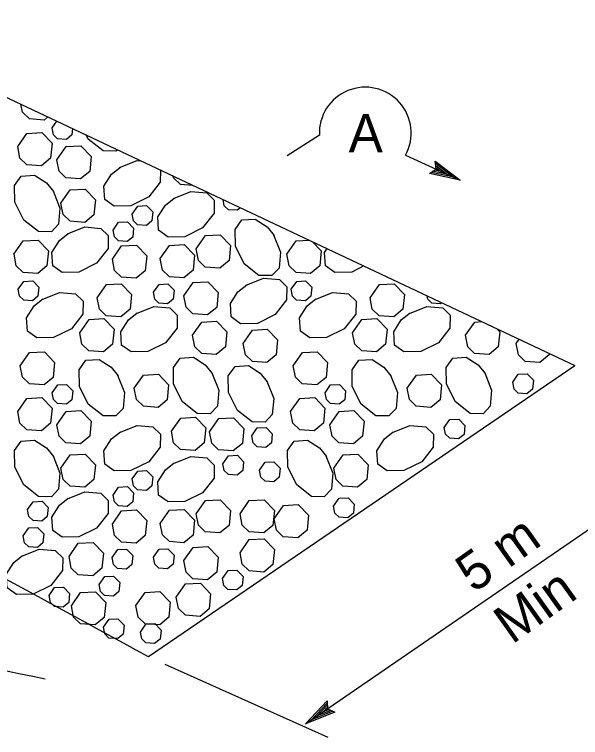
# Model space of a CAD drawing. Extents: x 6707406 to 6714471, y 1868570 to 1872341.
# Drawn here: x 6710751.9 to 6710858.1, y 1870263.6 to 1870399.2 of the extents above; entities that cross this region are included whole.
import ezdxf

# ---------------------------------------------------------------- set-up
doc = ezdxf.new("R2010")
doc.units = 0
for name, color, linetype in [('56 Stg 3 Anno', 7, 'Continuous'), ('57 Undefined', 7, 'Continuous'), ('60 Nongeo Data', 7, 'Continuous')]:
    doc.layers.add(name, color=color, linetype=linetype)

msp = doc.modelspace()

# ---------------------------------------------------------------- linework, layer by layer
at = {"layer": '56 Stg 3 Anno'}
for p, q in [((6710809.08, 1870376.54), (6710803.05, 1870372.66)), ((6710825.26, 1870372.79), (6710835.51, 1870368.07)), ((6710830.97, 1870370.16), (6710830.81, 1870371.65)), ((6710830.81, 1870371.65), (6710830.81, 1870371.65)), ((6710830.81, 1870371.65), (6710835.51, 1870368.07)), ((6710830.86, 1870371.26), (6710834.31, 1870368.63)), ((6710830.92, 1870370.85), (6710833.1, 1870369.18)), ((6710830.94, 1870370.47), (6710831.9, 1870369.74)), ((6710829.74, 1870369.32), (6710830.97, 1870370.16)), ((6710835.51, 1870368.07), (6710829.74, 1870369.32)), ((6710829.74, 1870369.32), (6710829.74, 1870369.32)), ((6710834.3, 1870368.63), (6710830.09, 1870369.54)), ((6710833.1, 1870369.18), (6710830.38, 1870369.77)), ((6710831.9, 1870369.74), (6710830.74, 1870369.99)), ((6710835.51, 1870368.07), (6710835.51, 1870368.07)), ((6710806.49, 1870266.16), (6710885.13, 1870320.15)), ((6710810.73, 1870263.58), (6710780.13, 1870277.31)), ((6710806.49, 1870266.16), (6710810.52, 1870270.48)), ((6710807.59, 1870266.92), (6710810.53, 1870270.06)), ((6710810.52, 1870270.48), (6710810.52, 1870270.48)), ((6710810.52, 1870270.48), (6710810.61, 1870268.99)), ((6710811.6, 1870268.53), (6710807.59, 1870266.91)), ((6710808.68, 1870267.66), (6710810.58, 1870269.69)), ((6710811.22, 1870268.68), (6710808.68, 1870267.66)), ((6710809.77, 1870268.41), (6710810.59, 1870269.28)), ((6710810.9, 1870268.86), (6710809.77, 1870268.41)), ((6710810.61, 1870268.99), (6710811.97, 1870268.36)), ((6710811.97, 1870268.36), (6710806.49, 1870266.16)), ((6710811.97, 1870268.36), (6710811.97, 1870268.36)), ((6710806.49, 1870266.16), (6710806.49, 1870266.16))]:
    msp.add_line(p, q, dxfattribs=at)
msp.add_arc((6710817.69, 1870376.91), 8.62, 331.4936, 182.464, dxfattribs=at)
at = {"layer": '60 Nongeo Data'}
for p, q in [((6710717.37, 1870399.17), (6710856.99, 1870333.37)), ((6710777.01, 1870278.8), (6710857.03, 1870333.34))]:
    msp.add_line(p, q, dxfattribs=at)
for points in [[(6710758.13, 1870379.96), (6710757.43, 1870379.37), (6710754.68, 1870379.57), (6710753.39, 1870380.82), (6710753.1, 1870382.33)], [(6710758.95, 1870377.9), (6710759.83, 1870379.16)], [(6710752.49, 1870374.38), (6710754.22, 1870376.85), (6710757, 1870377.01), (6710758.93, 1870375.01), (6710758.65, 1870372.2), (6710756.94, 1870370.78), (6710754.19, 1870370.98), (6710752.91, 1870372.23), (6710752.49, 1870374.38)], [(6710762.77, 1870377.78), (6710762.65, 1870376.6), (6710761.62, 1870375.74), (6710759.97, 1870375.86), (6710759.2, 1870376.61), (6710758.95, 1870377.9)], [(6710771.16, 1870373.82), (6710770.91, 1870373.56), (6710768.49, 1870373.6), (6710765.73, 1870375.76), (6710765.33, 1870376.57)], [(6710759.83, 1870371.92), (6710761.57, 1870374.39), (6710764.35, 1870374.55), (6710766.28, 1870372.55), (6710766, 1870369.75), (6710764.29, 1870368.32), (6710761.54, 1870368.52), (6710760.26, 1870369.77), (6710759.84, 1870371.92)], [(6710771.61, 1870370.47), (6710774.87, 1870371.76), (6710775.68, 1870371.69)], [(6710779.27, 1870370), (6710779.23, 1870367.72), (6710777.08, 1870364.97), (6710773.74, 1870363.3), (6710770.6, 1870363.25), (6710768.84, 1870364.5), (6710768.67, 1870367), (6710770.1, 1870369.24), (6710771.75, 1870370.55)], [(6710759.13, 1870366.07), (6710760.42, 1870362.82), (6710760.16, 1870359.83), (6710758.81, 1870358.41), (6710756.39, 1870358.45), (6710753.63, 1870360.61), (6710751.96, 1870363.94), (6710751.91, 1870367.08), (6710753.16, 1870368.85), (6710755.67, 1870369.02), (6710757.9, 1870367.58), (6710759.21, 1870365.94)], [(6710785.37, 1870367.12), (6710783.03, 1870367.29), (6710781.74, 1870368.54), (6710781.67, 1870368.86)], [(6710760.61, 1870363.78), (6710762.35, 1870366.26), (6710765.13, 1870366.41), (6710767.06, 1870364.41), (6710766.78, 1870361.61), (6710765.06, 1870360.18), (6710762.32, 1870360.38), (6710761.03, 1870361.63), (6710760.61, 1870363.78)], [(6710781.71, 1870364.66), (6710784.96, 1870365.95), (6710787.95, 1870365.69), (6710789.37, 1870364.34), (6710789.33, 1870361.91), (6710787.17, 1870359.15), (6710783.84, 1870357.49), (6710780.7, 1870357.43), (6710778.93, 1870358.69), (6710778.76, 1870361.19), (6710780.2, 1870363.43), (6710781.84, 1870364.74)], [(6710794.26, 1870362.93), (6710793.67, 1870362.44), (6710792.03, 1870362.56), (6710791.25, 1870363.31), (6710791.03, 1870364.45)], [(6710773.96, 1870361.75), (6710775, 1870363.24), (6710776.67, 1870363.33), (6710777.82, 1870362.13), (6710777.66, 1870360.45), (6710776.63, 1870359.59), (6710774.98, 1870359.71), (6710774.21, 1870360.46), (6710773.96, 1870361.75)], [(6710800.48, 1870357.86), (6710801.77, 1870354.61), (6710801.51, 1870351.62), (6710800.16, 1870350.2), (6710797.74, 1870350.24), (6710794.98, 1870352.4), (6710793.32, 1870355.73), (6710793.26, 1870358.87), (6710794.52, 1870360.64), (6710797.02, 1870360.81), (6710799.26, 1870359.37), (6710800.57, 1870357.73)], [(6710770.37, 1870358.73), (6710771.41, 1870360.22), (6710773.08, 1870360.31), (6710774.24, 1870359.11), (6710774.07, 1870357.43), (6710773.04, 1870356.57), (6710771.39, 1870356.69), (6710770.62, 1870357.44), (6710770.37, 1870358.73)], [(6710761.82, 1870358.03), (6710765.08, 1870359.32), (6710768.07, 1870359.06), (6710769.49, 1870357.71), (6710769.44, 1870355.28), (6710767.29, 1870352.53), (6710763.96, 1870350.86), (6710760.81, 1870350.81), (6710759.05, 1870352.06), (6710758.88, 1870354.56), (6710760.31, 1870356.8), (6710761.96, 1870358.11)], [(6710751.79, 1870354.21), (6710753.53, 1870356.69), (6710756.31, 1870356.85), (6710758.24, 1870354.84), (6710757.96, 1870352.04), (6710756.25, 1870350.61), (6710753.5, 1870350.81), (6710752.21, 1870352.06), (6710751.8, 1870354.21)], [(6710785.97, 1870355.21), (6710787.71, 1870357.69), (6710790.49, 1870357.85), (6710792.42, 1870355.84), (6710792.14, 1870353.04), (6710790.42, 1870351.61), (6710787.68, 1870351.81), (6710786.39, 1870353.06), (6710785.97, 1870355.21)], [(6710802.99, 1870354.21), (6710804.73, 1870356.69), (6710807.21, 1870356.83)], [(6710770.25, 1870353.3), (6710771.99, 1870355.77), (6710774.77, 1870355.93), (6710776.7, 1870353.93), (6710776.42, 1870351.12), (6710774.7, 1870349.69), (6710771.96, 1870349.89), (6710770.67, 1870351.14), (6710770.25, 1870353.29)], [(6710779.22, 1870353.4), (6710780.96, 1870355.87), (6710783.74, 1870356.03), (6710785.67, 1870354.03), (6710785.39, 1870351.22), (6710783.68, 1870349.8), (6710780.94, 1870350), (6710779.65, 1870351.25), (6710779.23, 1870353.4)], [(6710807.78, 1870356.56), (6710809.43, 1870354.84), (6710809.16, 1870352.04), (6710807.44, 1870350.61), (6710804.7, 1870350.81), (6710803.41, 1870352.06), (6710802.99, 1870354.21)], [(6710817.44, 1870352.01), (6710815.15, 1870350.86), (6710812.01, 1870350.81), (6710810.24, 1870352.06), (6710810.07, 1870354.56), (6710810.52, 1870355.27)], [(6710752.59, 1870347.64), (6710753.63, 1870349.12), (6710755.3, 1870349.22), (6710756.45, 1870348.02), (6710756.29, 1870346.33), (6710755.26, 1870345.48), (6710753.61, 1870345.6), (6710752.84, 1870346.35), (6710752.59, 1870347.64)], [(6710767.4, 1870346.05), (6710769.14, 1870348.52), (6710771.91, 1870348.68), (6710773.85, 1870346.68), (6710773.57, 1870343.88), (6710771.85, 1870342.45), (6710769.11, 1870342.65), (6710767.82, 1870343.9), (6710767.4, 1870346.05)], [(6710777.95, 1870347.07), (6710779, 1870348.55), (6710780.66, 1870348.65), (6710781.82, 1870347.45), (6710781.65, 1870345.76), (6710780.62, 1870344.91), (6710778.98, 1870345.03), (6710778.2, 1870345.78), (6710777.95, 1870347.07)], [(6710783.65, 1870346.43), (6710785.39, 1870348.9), (6710788.17, 1870349.06), (6710790.1, 1870347.06), (6710789.82, 1870344.25), (6710788.1, 1870342.83), (6710785.36, 1870343.02), (6710784.07, 1870344.28), (6710783.65, 1870346.43)], [(6710795.32, 1870348.4), (6710798.58, 1870349.69), (6710801.57, 1870349.44), (6710802.99, 1870348.09), (6710802.94, 1870345.66), (6710800.79, 1870342.9), (6710797.45, 1870341.24), (6710794.31, 1870341.18), (6710792.55, 1870342.44), (6710792.38, 1870344.94), (6710793.81, 1870347.18), (6710795.46, 1870348.49)], [(6710803.78, 1870347.64), (6710804.82, 1870349.12), (6710806.49, 1870349.22), (6710807.65, 1870348.02), (6710807.48, 1870346.33), (6710806.45, 1870345.48), (6710804.81, 1870345.6), (6710804.03, 1870346.35), (6710803.78, 1870347.64)], [(6710818.59, 1870346.05), (6710820.33, 1870348.52), (6710823.11, 1870348.68), (6710825.04, 1870346.68), (6710824.76, 1870343.88), (6710823.04, 1870342.45), (6710820.3, 1870342.65), (6710819.01, 1870343.9), (6710818.59, 1870346.05)], [(6710757.09, 1870345.73), (6710760.35, 1870347.02), (6710763.34, 1870346.77), (6710764.76, 1870345.42), (6710764.71, 1870342.99), (6710762.56, 1870340.23), (6710759.22, 1870338.57), (6710756.08, 1870338.51), (6710754.32, 1870339.77), (6710754.15, 1870342.27), (6710755.58, 1870344.51), (6710757.23, 1870345.82)], [(6710808.29, 1870345.73), (6710811.54, 1870347.02), (6710814.53, 1870346.77), (6710815.95, 1870345.42), (6710815.9, 1870342.99), (6710813.75, 1870340.23), (6710810.42, 1870338.57), (6710807.28, 1870338.51), (6710805.51, 1870339.77), (6710805.34, 1870342.27), (6710806.78, 1870344.51), (6710808.42, 1870345.82)], [(6710832.07, 1870345.11), (6710831.82, 1870344.91), (6710830.17, 1870345.03), (6710829.4, 1870345.78), (6710829.27, 1870346.43)], [(6710774.77, 1870343.1), (6710778.02, 1870344.39), (6710781.01, 1870344.13), (6710782.43, 1870342.78), (6710782.39, 1870340.36), (6710780.23, 1870337.6), (6710776.9, 1870335.94), (6710773.76, 1870335.88), (6710771.99, 1870337.14), (6710771.83, 1870339.64), (6710773.26, 1870341.88), (6710774.9, 1870343.19)], [(6710825.96, 1870343.1), (6710829.22, 1870344.39), (6710832.21, 1870344.13), (6710833.63, 1870342.78), (6710833.58, 1870340.36), (6710831.43, 1870337.6), (6710828.09, 1870335.94), (6710824.95, 1870335.88), (6710823.19, 1870337.14), (6710823.02, 1870339.64), (6710824.45, 1870341.88), (6710826.1, 1870343.19)], [(6710764.13, 1870339.5), (6710765.87, 1870341.98), (6710768.64, 1870342.14), (6710770.57, 1870340.14), (6710770.29, 1870337.33), (6710768.58, 1870335.9), (6710765.84, 1870336.1), (6710764.55, 1870337.35), (6710764.13, 1870339.5)], [(6710815.32, 1870339.5), (6710817.06, 1870341.98), (6710819.84, 1870342.14), (6710821.77, 1870340.14), (6710821.49, 1870337.33), (6710819.77, 1870335.9), (6710817.03, 1870336.1), (6710815.74, 1870337.35), (6710815.32, 1870339.5)], [(6710785.29, 1870339.02), (6710787.03, 1870341.49), (6710789.81, 1870341.65), (6710791.74, 1870339.65), (6710791.46, 1870336.85), (6710789.74, 1870335.42), (6710787, 1870335.62), (6710785.71, 1870336.87), (6710785.29, 1870339.02)], [(6710836.48, 1870339.02), (6710838.22, 1870341.49), (6710839.58, 1870341.57)], [(6710794.8, 1870337.5), (6710796.54, 1870339.98), (6710799.31, 1870340.14), (6710801.24, 1870338.14), (6710800.97, 1870335.33), (6710799.25, 1870333.9), (6710796.51, 1870334.1), (6710795.22, 1870335.35), (6710794.8, 1870337.5)], [(6710842.32, 1870340.28), (6710842.93, 1870339.65), (6710842.65, 1870336.85), (6710840.93, 1870335.42), (6710838.19, 1870335.62), (6710836.9, 1870336.87), (6710836.48, 1870339.02)], [(6710845.99, 1870337.5), (6710846.54, 1870338.29)], [(6710852.19, 1870335.63), (6710852.16, 1870335.33), (6710850.44, 1870333.9), (6710847.7, 1870334.1), (6710846.41, 1870335.35), (6710845.99, 1870337.5)], [(6710752.97, 1870333.3), (6710754.71, 1870335.77), (6710757.49, 1870335.93), (6710759.42, 1870333.93), (6710759.14, 1870331.12), (6710757.43, 1870329.7), (6710754.68, 1870329.89), (6710753.39, 1870331.15), (6710752.97, 1870333.3)], [(6710804.17, 1870333.3), (6710805.91, 1870335.77), (6710808.68, 1870335.93), (6710810.61, 1870333.93), (6710810.33, 1870331.12), (6710808.62, 1870329.7), (6710805.88, 1870329.89), (6710804.59, 1870331.15), (6710804.17, 1870333.3)], [(6710771.23, 1870331.55), (6710772.52, 1870328.3), (6710772.26, 1870325.31), (6710770.91, 1870323.89), (6710768.49, 1870323.93), (6710765.73, 1870326.09), (6710764.07, 1870329.42), (6710764.01, 1870332.56), (6710765.27, 1870334.33), (6710767.77, 1870334.49), (6710770, 1870333.06), (6710771.31, 1870331.42)], [(6710788.91, 1870331.97), (6710790.2, 1870328.72), (6710789.94, 1870325.73), (6710788.59, 1870324.31), (6710786.16, 1870324.35), (6710783.41, 1870326.51), (6710781.74, 1870329.84), (6710781.69, 1870332.98), (6710782.94, 1870334.75), (6710785.44, 1870334.92), (6710787.68, 1870333.48), (6710788.99, 1870331.84)], [(6710822.42, 1870331.55), (6710823.71, 1870328.3), (6710823.46, 1870325.31), (6710822.11, 1870323.89), (6710819.68, 1870323.93), (6710816.92, 1870326.09), (6710815.26, 1870329.42), (6710815.2, 1870332.56), (6710816.46, 1870334.33), (6710818.96, 1870334.49), (6710821.2, 1870333.06), (6710822.51, 1870331.42)], [(6710840.1, 1870331.97), (6710841.39, 1870328.72), (6710841.13, 1870325.73), (6710839.78, 1870324.31), (6710837.36, 1870324.35), (6710834.6, 1870326.51), (6710832.94, 1870329.84), (6710832.88, 1870332.98), (6710834.14, 1870334.75), (6710836.64, 1870334.92), (6710838.87, 1870333.48), (6710840.18, 1870331.84)], [(6710799.22, 1870330.39), (6710800.51, 1870327.14), (6710800.25, 1870324.15), (6710798.9, 1870322.73), (6710796.48, 1870322.77), (6710793.72, 1870324.93), (6710792.05, 1870328.26), (6710792, 1870331.4), (6710793.26, 1870333.17), (6710795.76, 1870333.34), (6710797.99, 1870331.9), (6710799.3, 1870330.26)], [(6710774.36, 1870329.09), (6710776.09, 1870331.56), (6710778.87, 1870331.72), (6710780.8, 1870329.72), (6710780.52, 1870326.92), (6710778.81, 1870325.49), (6710776.07, 1870325.69), (6710774.78, 1870326.94), (6710774.36, 1870329.09)], [(6710825.55, 1870329.09), (6710827.29, 1870331.56), (6710830.06, 1870331.72), (6710832, 1870329.72), (6710831.72, 1870326.92), (6710830, 1870325.49), (6710827.26, 1870325.69), (6710825.97, 1870326.94), (6710825.55, 1870329.09)], [(6710845.35, 1870330.21), (6710846.39, 1870331.7), (6710848.06, 1870331.79), (6710849.22, 1870330.59), (6710849.05, 1870328.91), (6710848.02, 1870328.05), (6710846.37, 1870328.17), (6710845.6, 1870328.92), (6710845.35, 1870330.21)], [(6710758.95, 1870328.23), (6710759.99, 1870329.71), (6710761.66, 1870329.81), (6710762.82, 1870328.61), (6710762.65, 1870326.92), (6710761.62, 1870326.07), (6710759.97, 1870326.19), (6710759.2, 1870326.94), (6710758.95, 1870328.23)], [(6710810.14, 1870328.23), (6710811.19, 1870329.71), (6710812.85, 1870329.81), (6710814.01, 1870328.61), (6710813.84, 1870326.92), (6710812.81, 1870326.07), (6710811.17, 1870326.19), (6710810.39, 1870326.94), (6710810.14, 1870328.23)], [(6710752.49, 1870324.71), (6710754.22, 1870327.18), (6710757, 1870327.34), (6710758.93, 1870325.34), (6710758.65, 1870322.53), (6710756.94, 1870321.1), (6710754.19, 1870321.3), (6710752.91, 1870322.55), (6710752.49, 1870324.7)], [(6710803.68, 1870324.71), (6710805.42, 1870327.18), (6710808.2, 1870327.34), (6710810.13, 1870325.34), (6710809.85, 1870322.53), (6710808.13, 1870321.1), (6710805.39, 1870321.3), (6710804.1, 1870322.55), (6710803.68, 1870324.7)], [(6710759.83, 1870322.25), (6710761.57, 1870324.72), (6710764.35, 1870324.88), (6710766.28, 1870322.88), (6710766, 1870320.07), (6710764.29, 1870318.65), (6710761.54, 1870318.85), (6710760.26, 1870320.1), (6710759.84, 1870322.25)], [(6710811.03, 1870322.25), (6710812.77, 1870324.72), (6710815.54, 1870324.88), (6710817.48, 1870322.88), (6710817.2, 1870320.07), (6710815.48, 1870318.65), (6710812.74, 1870318.85), (6710811.45, 1870320.1), (6710811.03, 1870322.25)], [(6710781.32, 1870321.02), (6710783.06, 1870323.5), (6710785.83, 1870323.66), (6710787.76, 1870321.65), (6710787.48, 1870318.85), (6710785.77, 1870317.42), (6710783.03, 1870317.62), (6710781.74, 1870318.87), (6710781.32, 1870321.02)], [(6710788.47, 1870320.92), (6710790.21, 1870323.39), (6710792.99, 1870323.55), (6710794.92, 1870321.55), (6710794.64, 1870318.74), (6710792.92, 1870317.32), (6710790.18, 1870317.52), (6710788.89, 1870318.77), (6710788.47, 1870320.92)], [(6710832.52, 1870321.73), (6710833.56, 1870323.22), (6710835.23, 1870323.31), (6710836.39, 1870322.11), (6710836.22, 1870320.43), (6710835.19, 1870319.57), (6710833.54, 1870319.69), (6710832.77, 1870320.44), (6710832.52, 1870321.73)], [(6710771.61, 1870320.8), (6710774.87, 1870322.09), (6710777.86, 1870321.83), (6710779.28, 1870320.48), (6710779.23, 1870318.05), (6710777.08, 1870315.3), (6710773.74, 1870313.63), (6710770.6, 1870313.57), (6710768.84, 1870314.83), (6710768.67, 1870317.33), (6710770.1, 1870319.57), (6710771.75, 1870320.88)], [(6710796.39, 1870320.15), (6710797.43, 1870321.64), (6710799.1, 1870321.73), (6710800.25, 1870320.53), (6710800.09, 1870318.85), (6710799.06, 1870317.99), (6710797.41, 1870318.11), (6710796.64, 1870318.86), (6710796.39, 1870320.15)], [(6710822.81, 1870320.8), (6710826.06, 1870322.09), (6710829.05, 1870321.83), (6710830.47, 1870320.48), (6710830.43, 1870318.05), (6710828.27, 1870315.3), (6710824.94, 1870313.63), (6710821.8, 1870313.57), (6710820.03, 1870314.83), (6710819.86, 1870317.33), (6710821.3, 1870319.57), (6710822.94, 1870320.88)], [(6710759.13, 1870316.4), (6710760.42, 1870313.14), (6710760.16, 1870310.15), (6710758.81, 1870308.73), (6710756.39, 1870308.78), (6710753.63, 1870310.94), (6710751.96, 1870314.27), (6710751.91, 1870317.41), (6710753.16, 1870319.18), (6710755.67, 1870319.34), (6710757.9, 1870317.91), (6710759.21, 1870316.27)], [(6710810.32, 1870316.4), (6710811.61, 1870313.14), (6710811.36, 1870310.15), (6710810, 1870308.73), (6710807.58, 1870308.78), (6710804.82, 1870310.94), (6710803.16, 1870314.27), (6710803.1, 1870317.41), (6710804.36, 1870319.18), (6710806.86, 1870319.34), (6710809.1, 1870317.91), (6710810.41, 1870316.27)], [(6710760.61, 1870314.11), (6710762.35, 1870316.58), (6710765.13, 1870316.74), (6710767.06, 1870314.74), (6710766.78, 1870311.94), (6710765.06, 1870310.51), (6710762.32, 1870310.71), (6710761.03, 1870311.96), (6710760.61, 1870314.11)], [(6710781.71, 1870314.98), (6710784.96, 1870316.27), (6710787.95, 1870316.02), (6710789.37, 1870314.66), (6710789.33, 1870312.24), (6710787.17, 1870309.48), (6710783.84, 1870307.82), (6710780.7, 1870307.76), (6710778.93, 1870309.02), (6710778.76, 1870311.52), (6710780.2, 1870313.76), (6710781.84, 1870315.07)], [(6710791, 1870314.93), (6710792.05, 1870316.42), (6710793.71, 1870316.51), (6710794.87, 1870315.31), (6710794.7, 1870313.63), (6710793.67, 1870312.77), (6710792.03, 1870312.89), (6710791.25, 1870313.64), (6710791, 1870314.93)], [(6710811.8, 1870314.11), (6710813.54, 1870316.58), (6710816.32, 1870316.74), (6710818.25, 1870314.74), (6710817.97, 1870311.94), (6710816.25, 1870310.51), (6710813.51, 1870310.71), (6710812.22, 1870311.96), (6710811.8, 1870314.11)], [(6710797.85, 1870313.71), (6710798.9, 1870315.19), (6710800.56, 1870315.29), (6710801.72, 1870314.09), (6710801.55, 1870312.41), (6710800.53, 1870311.55), (6710798.88, 1870311.67), (6710798.1, 1870312.42), (6710797.85, 1870313.71)], [(6710773.96, 1870312.08), (6710775, 1870313.56), (6710776.67, 1870313.66), (6710777.82, 1870312.46), (6710777.66, 1870310.77), (6710776.63, 1870309.92), (6710774.98, 1870310.04), (6710774.21, 1870310.79), (6710773.96, 1870312.08)], [(6710770.37, 1870309.06), (6710771.41, 1870310.55), (6710773.08, 1870310.64), (6710774.24, 1870309.44), (6710774.07, 1870307.76), (6710773.04, 1870306.9), (6710771.39, 1870307.02), (6710770.62, 1870307.77), (6710770.37, 1870309.06)], [(6710761.82, 1870308.36), (6710765.08, 1870309.65), (6710768.07, 1870309.39), (6710769.49, 1870308.04), (6710769.44, 1870305.61), (6710767.29, 1870302.86), (6710763.96, 1870301.19), (6710760.81, 1870301.13), (6710759.05, 1870302.39), (6710758.88, 1870304.89), (6710760.31, 1870307.13), (6710761.96, 1870308.44)], [(6710754.34, 1870306.33), (6710755.39, 1870307.81), (6710757.05, 1870307.9), (6710758.21, 1870306.7), (6710758.04, 1870305.02), (6710757.02, 1870304.16), (6710755.37, 1870304.28), (6710754.6, 1870305.03), (6710754.34, 1870306.32)], [(6710785.97, 1870305.54), (6710787.71, 1870308.01), (6710790.49, 1870308.17), (6710792.42, 1870306.17), (6710792.14, 1870303.37), (6710790.42, 1870301.94), (6710787.68, 1870302.14), (6710786.39, 1870303.39), (6710785.97, 1870305.54)], [(6710794.2, 1870305.54), (6710795.94, 1870308.01), (6710798.72, 1870308.17), (6710800.65, 1870306.17), (6710800.37, 1870303.37), (6710798.65, 1870301.94), (6710795.91, 1870302.14), (6710794.62, 1870303.39), (6710794.2, 1870305.54)], [(6710811.75, 1870306.96), (6710812.8, 1870308.45), (6710814.46, 1870308.54), (6710815.62, 1870307.34), (6710815.45, 1870305.66), (6710814.43, 1870304.8), (6710812.78, 1870304.92), (6710812.01, 1870305.67), (6710811.76, 1870306.96)], [(6710800.6, 1870304.62), (6710802.34, 1870307.1), (6710805.12, 1870307.26), (6710807.05, 1870305.26), (6710806.77, 1870302.45), (6710805.05, 1870301.02), (6710802.31, 1870301.22), (6710801.02, 1870302.47), (6710800.6, 1870304.62)], [(6710770.25, 1870303.62), (6710771.99, 1870306.1), (6710774.77, 1870306.26), (6710776.7, 1870304.25), (6710776.42, 1870301.45), (6710774.7, 1870300.02), (6710771.96, 1870300.22), (6710770.67, 1870301.47), (6710770.25, 1870303.62)], [(6710779.22, 1870303.73), (6710780.96, 1870306.2), (6710783.74, 1870306.36), (6710785.67, 1870304.36), (6710785.39, 1870301.55), (6710783.68, 1870300.12), (6710780.94, 1870300.32), (6710779.65, 1870301.57), (6710779.23, 1870303.72)], [(6710753.52, 1870301.4), (6710754.57, 1870302.89), (6710756.23, 1870302.98), (6710757.39, 1870301.78), (6710757.22, 1870300.1), (6710756.2, 1870299.24), (6710754.55, 1870299.36), (6710753.78, 1870300.11), (6710753.52, 1870301.4)], [(6710762.12, 1870297.52), (6710763.86, 1870300), (6710766.64, 1870300.16), (6710768.57, 1870298.15), (6710768.29, 1870295.35), (6710766.58, 1870293.92), (6710763.83, 1870294.12), (6710762.54, 1870295.37), (6710762.13, 1870297.52)], [(6710794.2, 1870298.22), (6710795.94, 1870300.69), (6710798.72, 1870300.85), (6710800.65, 1870298.85), (6710800.37, 1870296.05), (6710798.65, 1870294.62), (6710795.91, 1870294.82), (6710794.62, 1870296.07), (6710794.2, 1870298.22)], [(6710753.27, 1870297.62), (6710756.53, 1870298.91), (6710759.51, 1870298.65), (6710760.94, 1870297.3), (6710760.89, 1870294.88), (6710758.73, 1870292.12), (6710755.4, 1870290.46), (6710752.26, 1870290.4), (6710750.49, 1870291.66), (6710750.33, 1870294.16), (6710751.76, 1870296.4), (6710753.4, 1870297.71)], [(6710770.21, 1870297.34), (6710771.26, 1870298.83), (6710772.92, 1870298.92), (6710774.08, 1870297.72), (6710773.91, 1870296.04), (6710772.88, 1870295.18), (6710771.24, 1870295.3), (6710770.46, 1870296.05), (6710770.21, 1870297.34)], [(6710777.95, 1870297.4), (6710779, 1870298.88), (6710780.66, 1870298.98), (6710781.82, 1870297.77), (6710781.65, 1870296.09), (6710780.62, 1870295.24), (6710778.98, 1870295.36), (6710778.2, 1870296.11), (6710777.95, 1870297.4)], [(6710783.65, 1870296.75), (6710785.39, 1870299.23), (6710788.17, 1870299.39), (6710790.1, 1870297.39), (6710789.82, 1870294.58), (6710788.1, 1870293.15), (6710785.36, 1870293.35), (6710784.07, 1870294.6), (6710783.65, 1870296.75)], [(6710790.89, 1870293.41), (6710791.94, 1870294.89), (6710793.6, 1870294.99), (6710794.76, 1870293.79), (6710794.6, 1870292.11), (6710793.57, 1870291.25), (6710791.92, 1870291.37), (6710791.15, 1870292.12), (6710790.9, 1870293.41)], [(6710767.78, 1870292.27), (6710768.82, 1870293.76), (6710770.49, 1870293.85), (6710771.65, 1870292.65), (6710771.48, 1870290.97), (6710770.45, 1870290.11), (6710768.8, 1870290.23), (6710768.03, 1870290.98), (6710767.78, 1870292.27)], [(6710758.36, 1870290.22), (6710759.4, 1870291.7), (6710761.07, 1870291.8), (6710762.23, 1870290.59), (6710762.06, 1870288.91), (6710761.03, 1870288.06), (6710759.39, 1870288.18), (6710758.61, 1870288.93), (6710758.36, 1870290.22)], [(6710782.24, 1870289.91), (6710783.98, 1870292.38), (6710786.75, 1870292.54), (6710788.68, 1870290.54), (6710788.41, 1870287.74), (6710786.69, 1870286.31), (6710783.95, 1870286.51), (6710782.66, 1870287.76), (6710782.24, 1870289.91)], [(6710762.55, 1870288.29), (6710764.29, 1870290.76), (6710767.06, 1870290.92), (6710768.99, 1870288.92), (6710768.71, 1870286.11), (6710767, 1870284.69), (6710764.26, 1870284.88), (6710762.97, 1870286.14), (6710762.55, 1870288.29)], [(6710774.67, 1870288.33), (6710776.41, 1870290.81), (6710779.18, 1870290.97), (6710781.12, 1870288.96), (6710780.84, 1870286.16), (6710779.12, 1870284.73), (6710776.38, 1870284.93), (6710775.09, 1870286.18), (6710774.67, 1870288.33)], [(6710768.58, 1870284.29), (6710769.62, 1870285.77), (6710771.29, 1870285.87), (6710772.44, 1870284.66), (6710772.28, 1870282.98), (6710771.25, 1870282.13), (6710769.6, 1870282.24), (6710768.83, 1870283), (6710768.58, 1870284.29)], [(6710775.51, 1870283.36), (6710776.55, 1870284.85), (6710778.22, 1870284.94), (6710779.38, 1870283.74), (6710779.21, 1870282.06), (6710778.18, 1870281.2), (6710776.53, 1870281.32), (6710775.76, 1870282.07), (6710775.51, 1870283.36)]]:
    msp.add_lwpolyline(points, dxfattribs=at)
for points in [[(6710505.99, 1870337.51), (6710532.99, 1870347.83), (6710590.83, 1870352.57), (6710625.79, 1870346.13), (6710776.97, 1870278.77)], [(6710757.64, 1870274.53), (6710720.56, 1870280.95), (6710700.05, 1870282.48)]]:
    msp.add_spline(points, degree=3, dxfattribs=at)

# ---------------------------------------------------------------- texts
at = {"layer": '57 Undefined'}
msp.add_text('A', height=7.21, dxfattribs=at).set_placement((6710814.55, 1870373.3))
for s, p in [('5 m', (6710838.04, 1870290.57)), ('Min', (6710845.22, 1870280.95))]:
    msp.add_text(s, height=7.2, rotation=35.4657, dxfattribs=at).set_placement(p)

doc.saveas('drawing.dxf')
